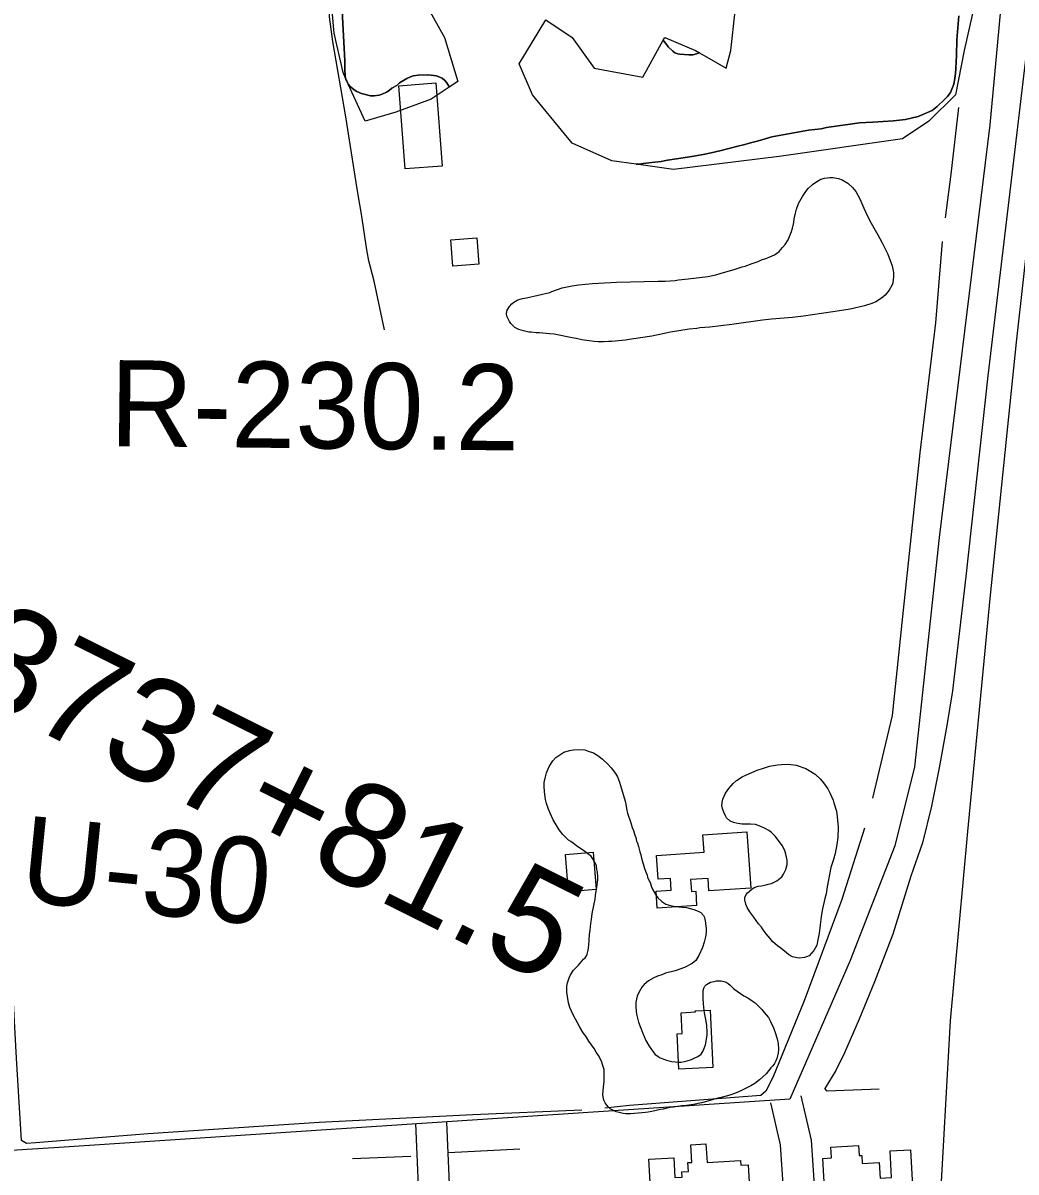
# Model space of a CAD drawing. Extents: x 3313447 to 3351316, y 703786 to 729172.
# Drawn here: x 3320930 to 3321887, y 714073 to 715181 of the extents above; entities that cross this region are included whole.
import ezdxf

# ---------------------------------------------------------------- set-up
doc = ezdxf.new("R2010")
doc.units = 0
for name, color, linetype in [('V-BLDG-OTLN', 7, 'Continuous'), ('V-DTCH-CNTR', 7, 'Continuous'), ('V-LEVE-TOET', 7, 'Continuous'), ('V-RIVR-RANG-IDEN', 7, 'Continuous'), ('V-ROAD-CNTR', 7, 'Continuous'), ('V-SITE-VEGE', 7, 'Continuous'), ('V-SURV-IDEN', 7, 'Continuous'), ('V-TOPO-SHOR', 7, 'Continuous')]:
    doc.layers.add(name, color=color, linetype=linetype)

msp = doc.modelspace()

# ---------------------------------------------------------------- linework, layer by layer
at = {"layer": 'V-BLDG-OTLN'}
for points in [[(3321327.5, 715123.3), (3321333.6, 715043.1), (3321297.9, 715040.4), (3321291.7, 715120.5)], [(3321342, 714972.1), (3321367.1, 714974), (3321369, 714948.5), (3321343.9, 714946.7)], [(3321627.2, 714401.1), (3321630.9, 714346.8), (3321590.7, 714344.1), (3321589.9, 714356.2), (3321573, 714355), (3321573.8, 714343.5), (3321577.9, 714343.7), (3321578.8, 714330), (3321540.8, 714327.4), (3321539.7, 714343.9), (3321554.3, 714344.8), (3321553.5, 714356.1), (3321541.7, 714355.3), (3321540.1, 714378.2), (3321585.9, 714381.3), (3321584.7, 714398.2)], [(3321455.2, 714343.2), (3321452.3, 714379.1), (3321479.1, 714381.3), (3321482, 714345.3)], [(3321594.4, 714173.8), (3321561.7, 714172.3), (3321560.1, 714206.2), (3321564.7, 714206.5), (3321563.8, 714226.6), (3321577.6, 714227.3), (3321577.5, 714228.5), (3321591.8, 714229.2)], [(3321622.6, 714051.2), (3321572.9, 714048.4), (3321572.5, 714055.3), (3321565.3, 714054.9), (3321564.9, 714061.4), (3321558.3, 714061), (3321559.1, 714047.8), (3321534.9, 714046.4), (3321532.7, 714085.2), (3321556.7, 714086.5), (3321557.7, 714067.7), (3321564.8, 714068.1), (3321564.5, 714073), (3321570.9, 714073.4), (3321570.4, 714082), (3321574.1, 714082.2), (3321573.1, 714099.3), (3321587.8, 714100.1), (3321588.8, 714082), (3321621.1, 714083.9), (3321621.4, 714079.5), (3321628.4, 714079.9), (3321629.6, 714057.3), (3321622.3, 714056.9)], [(3321703.7, 714029.1), (3321700.5, 714086.1), (3321708.9, 714086.6), (3321708.3, 714096.9), (3321734.7, 714098.4), (3321735.3, 714088.9), (3321737.9, 714089), (3321738.3, 714081.2), (3321754.7, 714082.1), (3321755.6, 714066.9), (3321766.7, 714067.5), (3321765.3, 714093.3), (3321784.8, 714094.4), (3321789.4, 714012.3), (3321711.6, 714007.9), (3321710.4, 714029.5)]]:
    msp.add_lwpolyline(points, close=True, dxfattribs=at)
at = {"layer": 'V-DTCH-CNTR'}
msp.add_lwpolyline([(3321278.1, 714885.1), (3321267.9, 714932), (3321262.8, 714951.9), (3321260.9, 714962.5), (3321255.9, 714996.8), (3321252.7, 715015.3), (3321250.8, 715027.2), (3321240.7, 715090.7), (3321228.1, 715163.4), (3321225, 715187.2), (3321223.1, 715285.6), (3321220.9, 715424.3), (3321216.9, 715500.2), (3321214.4, 715520.1), (3321213.2, 715540.5), (3321213.3, 715547.8), (3321226.3, 715603.8), (3321257.4, 715706.6), (3321261.6, 715725), (3321262.3, 715737.6), (3321261.8, 715750.2)], dxfattribs=at)
at = {"layer": 'V-LEVE-TOET'}
msp.add_lwpolyline([(3322242.7, 717499.5), (3322230.5, 717440.1), (3322212.4, 717370.3), (3322147.4, 717157.3), (3322074.9, 716954), (3322061.5, 716913.3), (3322054.1, 716881.2), (3322048.8, 716841), (3322042.9, 716778.8), (3322030.3, 716614.9), (3322015.8, 716405.6), (3321998.4, 716162.8), (3321980.6, 715959.1), (3321966.7, 715741.7), (3321955.2, 715572.1), (3321934, 715358.8), (3321913.8, 715115), (3321886.9, 714873.2), (3321861.3, 714626.1), (3321839.8, 714401.3), (3321823, 714218.9), (3321812.7, 714029.1)], dxfattribs=at)
at = {"layer": 'V-ROAD-CNTR'}
for points in [[(3322085.6, 717177.5), (3322015.6, 716972.5), (3322011.3, 716929.5), (3321982.2, 716607.2), (3321954.7, 716329.7), (3321908.3, 715769.3), (3321893.7, 715433.5), (3321861.3, 715083), (3321812.5, 714684.9), (3321788.9, 714463.9), (3321769.7, 714387.5), (3321726.9, 714277.1), (3321668.7, 714143.2), (3320964.4, 714096.5), (3320401.5, 714061.2), (3320028.1, 714032.5), (3319482.1, 714000.4), (3319185.8, 713985.2), (3318680.1, 713949.5), (3318059.6, 713912.2), (3317624.2, 713887.5), (3317588.3, 713886.1)], [(3321378, 713400.2), (3321715.2, 713421.7), (3321740.9, 713461), (3321742.6, 713511.5), (3321708.4, 713764.9), (3321705.6, 713861.5), (3321689.5, 714103.7), (3321679.7, 714146.3)], [(3321677.1, 713810.2), (3321675.6, 713860.1), (3321659.7, 714099.3), (3321650.4, 714139.6)], [(3321337.8, 714120.9), (3321351.7, 713800.1), (3321353.4, 713784.7)], [(3321307.9, 714119.6), (3321321.8, 713797.8), (3321331.8, 713706.9), (3321334, 713663.7)]]:
    msp.add_lwpolyline(points, dxfattribs=at)
at = {"layer": 'V-SITE-VEGE'}
for points in [[(3321230.5, 715319.4), (3321239.8, 715144.7), (3321239.7, 715136.6), (3321240.1, 715130.2), (3321240.4, 715128.1), (3321238.1, 715133.3), (3321229.6, 715171.5), (3321225.3, 715218.2)], [(3321336.2, 715125.6), (3321333.6, 715128.1), (3321328.2, 715130.1), (3321323.1, 715130.9), (3321319.7, 715131.2), (3321310.5, 715130.8), (3321305.6, 715130.1), (3321303, 715129.3), (3321299.4, 715127.7), (3321292.5, 715123.3), (3321289.7, 715121), (3321285.2, 715118.2), (3321282.6, 715116.2), (3321279.8, 715114.6), (3321275.7, 715112.6), (3321272.7, 715111.6), (3321268.1, 715110.9), (3321264.6, 715110.9), (3321255.8, 715113), (3321251.2, 715115.2), (3321248.8, 715116.8), (3321245, 715119.9), (3321243.1, 715122.2), (3321240.4, 715128.1), (3321240.1, 715130.2), (3321239.7, 715136.6), (3321239.8, 715144.7), (3321230.5, 715319.4)], [(3321862.2, 715269.2), (3321836.7, 715154.5), (3321828.2, 715112), (3321802.7, 715086.5), (3321777.3, 715069.5), (3321658.4, 715052.5), (3321556.5, 715039.8), (3321520.6, 715044.9), (3321523, 715045.1), (3321527.3, 715045.5), (3321538.5, 715046.8), (3321544.6, 715047.7), (3321547.4, 715048.3), (3321550.6, 715048.7), (3321559.5, 715050), (3321574.2, 715052.5), (3321585.1, 715054.3), (3321592.7, 715055.8), (3321602.6, 715058.3), (3321617.1, 715061.9), (3321625.2, 715064), (3321630.6, 715065.6), (3321638.5, 715067.5), (3321651.2, 715071.4), (3321686.6, 715077.8), (3321698.9, 715079.1), (3321704, 715080.3), (3321735.8, 715084.9), (3321748.5, 715085.4), (3321768.6, 715086.8), (3321780.1, 715088.1), (3321792.4, 715090.9), (3321805.7, 715096.8), (3321810.5, 715100.6), (3321818, 715107.8), (3321820.7, 715110.2), (3321823.5, 715114.2), (3321826.6, 715122), (3321827.4, 715125.8), (3321828.3, 715132.4), (3321828.5, 715137.2), (3321829.4, 715150.1), (3321829.5, 715165), (3321831.5, 715188.1)], [(3321314.5, 715205.5), (3321335.7, 715167.2), (3321348.5, 715124.8), (3321340.3, 715119.3), (3321340, 715120.2), (3321338, 715123.6), (3321336.2, 715125.6)], [(3321559.5, 715050), (3321550.6, 715048.7), (3321547.4, 715048.3), (3321544.6, 715047.7), (3321538.5, 715046.8), (3321527.3, 715045.5), (3321523, 715045.1), (3321520.6, 715044.9), (3321497.1, 715048.3), (3321458.8, 715065.3), (3321420.6, 715112), (3321407.9, 715141.8), (3321433.4, 715184.2), (3321458.8, 715167.2), (3321480.1, 715137.5), (3321526.8, 715129), (3321546.5, 715164.5), (3321547.5, 715163.2), (3321549.1, 715161.4), (3321551.5, 715158.3), (3321555.9, 715153.9), (3321557.9, 715152.4), (3321560.7, 715151.4), (3321562.7, 715151), (3321571.3, 715150.3), (3321575, 715150.5), (3321578.8, 715151.3), (3321581.5, 715152.4), (3321607.4, 715137.5), (3321611.7, 715154.5), (3321615.9, 715192.7)], [(3321831.5, 715188.1), (3321829.5, 715165), (3321829.4, 715150.1), (3321828.5, 715137.2), (3321828.3, 715132.4), (3321827.4, 715125.8), (3321826.6, 715122), (3321823.5, 715114.2), (3321820.7, 715110.2), (3321818, 715107.8), (3321810.5, 715100.6), (3321805.7, 715096.8), (3321792.4, 715090.9), (3321780.1, 715088.1), (3321768.6, 715086.8), (3321748.5, 715085.4), (3321735.8, 715084.9), (3321704, 715080.3), (3321698.9, 715079.1), (3321686.6, 715077.8), (3321651.2, 715071.4), (3321638.5, 715067.5), (3321630.6, 715065.6), (3321625.2, 715064), (3321617.1, 715061.9), (3321602.6, 715058.3), (3321592.7, 715055.8), (3321585.1, 715054.3), (3321574.2, 715052.5), (3321559.5, 715050)], [(3321412, 714884.1), (3321407.5, 714885.4), (3321403.6, 714887.5), (3321399.7, 714891.4), (3321398.4, 714893.4), (3321396.8, 714896.5), (3321396, 714898.5), (3321395.5, 714901), (3321396.1, 714904.2), (3321398.4, 714907.8), (3321400.6, 714910.3), (3321402.6, 714911.8), (3321406.5, 714914), (3321411, 714915.3), (3321414.9, 714916), (3321437.3, 714921.2), (3321439.1, 714922.1), (3321449.2, 714925.8), (3321458.9, 714927.8), (3321464.9, 714928.5), (3321478.4, 714929.8), (3321501.7, 714931.2), (3321541.7, 714932), (3321548.4, 714932.2), (3321558.2, 714932.9), (3321561.3, 714933.3), (3321570.5, 714934.3), (3321589.5, 714936.7), (3321597.2, 714938.4), (3321601.6, 714939.7), (3321615.8, 714943.7), (3321622.6, 714945.9), (3321625.6, 714946.7), (3321632.4, 714949.2), (3321638.2, 714951.1), (3321641.4, 714952.6), (3321646.3, 714954.5), (3321649.5, 714955.6), (3321653.7, 714957.5), (3321658.4, 714960.9), (3321661.7, 714964.6), (3321664, 714967.4), (3321666.9, 714971.9), (3321668.4, 714975.2), (3321670.2, 714980), (3321671.3, 714983.4), (3321672.4, 714988.8), (3321672.9, 714992.4), (3321674, 714997.9), (3321675, 715001.7), (3321676.9, 715007.2), (3321680.7, 715013.9), (3321684, 715018.5), (3321686.4, 715021.5), (3321690.5, 715025.4), (3321693.8, 715027.7), (3321698.6, 715030.4), (3321702.1, 715031.4), (3321707.2, 715032.3), (3321710.5, 715032.3), (3321715.6, 715031.2), (3321719.2, 715029.8), (3321724.5, 715026.8), (3321729.1, 715022.4), (3321732.3, 715018.5), (3321736, 715011.7), (3321739.9, 715002.5), (3321742, 714998.4), (3321744.8, 714992.3), (3321746.9, 714988.2), (3321753.4, 714976.9), (3321757.4, 714969.7), (3321760.9, 714962.8), (3321763, 714958.3), (3321767.1, 714946.8), (3321768.4, 714940.4), (3321768.6, 714936.2), (3321767.9, 714930.6), (3321767.1, 714928.7), (3321764.5, 714923.6), (3321760.4, 714918.6), (3321756.9, 714915.7), (3321751.4, 714912.3), (3321747.5, 714910.6), (3321740.5, 714908.4), (3321726.7, 714905.3), (3321712.2, 714902.8), (3321699, 714901.1), (3321681.7, 714898.5), (3321671.1, 714897.2), (3321651, 714895.6), (3321642.4, 714894.6), (3321612.7, 714890.5), (3321591.4, 714887.8), (3321582, 714887), (3321579, 714886.6), (3321571.5, 714885.9), (3321553.6, 714883), (3321546.2, 714881.4), (3321535.6, 714879), (3321515.9, 714876.1)], [(3321515.9, 714876.1), (3321510.2, 714875.4), (3321506.9, 714874.8), (3321496.7, 714874), (3321493.9, 714873.9), (3321489.1, 714873.8), (3321483.8, 714873.8), (3321480.2, 714874.1), (3321475.3, 714874.6), (3321468, 714875.7), (3321462.6, 714876.7), (3321458.8, 714877.6), (3321441.6, 714880.9), (3321437, 714881.5), (3321427.5, 714882.2), (3321424.2, 714882.2), (3321419.3, 714882.9), (3321417.2, 714883), (3321412, 714884.1)], [(3321476.7, 714377.9), (3321474.4, 714379.6), (3321471.2, 714382.2), (3321463.1, 714387.6), (3321459.8, 714390), (3321457.7, 714391.6), (3321455.4, 714393), (3321452.4, 714395.9), (3321449.8, 714398.5), (3321446.4, 714402.9), (3321440.6, 714412.5), (3321437.6, 714418.9), (3321436, 714422.8), (3321434, 714428.4), (3321433.1, 714432.2), (3321432.2, 714439.7), (3321431.8, 714445), (3321432, 714448.5), (3321433, 714454.1), (3321434, 714458.1), (3321436.6, 714464.1), (3321440.1, 714469.5), (3321443, 714472.7), (3321447.9, 714475.9), (3321450.9, 714477.8), (3321456.3, 714479.4), (3321460, 714480), (3321464.7, 714480.5), (3321471.2, 714480), (3321474.3, 714479), (3321479.4, 714477.1), (3321484.5, 714474), (3321488.2, 714471), (3321493.3, 714466.2), (3321496.5, 714462.7), (3321500.5, 714457.3), (3321502.5, 714454), (3321504.4, 714449.1), (3321505.5, 714445.6), (3321509.8, 714430.7), (3321510.5, 714427.6), (3321511.4, 714421.5), (3321512.1, 714419), (3321515.3, 714409.6), (3321516.6, 714405.2), (3321517.8, 714402.4), (3321519.1, 714397.9), (3321520.3, 714395.6)], [(3321696.9, 714303.2), (3321695.7, 714296.9), (3321694.5, 714291.8), (3321693, 714288.8), (3321691.6, 714286.7), (3321689.5, 714283.9), (3321687.2, 714281.6), (3321684.8, 714280.4), (3321682.7, 714279.7), (3321677.8, 714279.3), (3321675.5, 714279.6), (3321671.3, 714280.5), (3321669.4, 714281.5), (3321667.3, 714282.7), (3321659.9, 714288.8), (3321656.7, 714291.1), (3321652.3, 714295.1), (3321649.7, 714298.2), (3321645.8, 714302.7), (3321642.8, 714306.4), (3321641.2, 714309), (3321638.4, 714312.3), (3321634, 714318.6), (3321631.9, 714321.2), (3321630.1, 714323.8), (3321627.6, 714328.2), (3321626.2, 714331.3), (3321625.3, 714335.5), (3321625.3, 714337.8), (3321626.5, 714340.6), (3321627.7, 714342.2), (3321631.9, 714345.9), (3321634.2, 714347.3), (3321638.2, 714348.5), (3321641.2, 714348.9), (3321645.7, 714349.8), (3321647.8, 714350.5), (3321651.1, 714351.1), (3321656.2, 714353.9), (3321660.9, 714357.8), (3321662.6, 714360.2), (3321664.7, 714364.6), (3321665.9, 714369.7), (3321665.9, 714373.7), (3321664.8, 714379.5), (3321663.7, 714383), (3321661.2, 714387.9), (3321656.8, 714394), (3321654.5, 714396.9), (3321651, 714400.4), (3321648.4, 714402.3), (3321644.7, 714404.4), (3321640.8, 714406.1), (3321635.6, 714408), (3321630.7, 714408.5), (3321628.4, 714408.3), (3321622.8, 714408.3), (3321620.5, 714408.8), (3321616.8, 714409.3), (3321614.2, 714410), (3321610.9, 714411.7), (3321607.7, 714414.5), (3321606.5, 714416.4), (3321604.9, 714420.1), (3321604, 714422.7), (3321603.1, 714425.7), (3321603.4, 714429.2), (3321604.1, 714432.7), (3321606.5, 714438.3), (3321609.8, 714442.7), (3321614, 714447.8), (3321617.3, 714450.6), (3321622.7, 714454), (3321626.7, 714456.1), (3321637.2, 714460.5), (3321643.1, 714462.5), (3321648.9, 714464.3), (3321656.6, 714465.7), (3321660.6, 714466.1), (3321666, 714466.3), (3321669.5, 714466), (3321674.6, 714465.3), (3321683.9, 714462), (3321687.4, 714460.3), (3321693, 714456.8), (3321698.1, 714451.8), (3321701.1, 714448.3), (3321705.2, 714442.4), (3321707.3, 714438.7), (3321710.3, 714431.6), (3321710.9, 714429.1), (3321713.7, 714421.1), (3321714.3, 714415.5), (3321715.2, 714405.7), (3321714.9, 714395.7), (3321713.9, 714388.9), (3321712.2, 714380.1), (3321710.7, 714374.5), (3321708.1, 714366.8), (3321704.5, 714347.9), (3321703.5, 714341.2)], [(3321520.3, 714395.6), (3321521, 714392.1), (3321521.9, 714390), (3321522.8, 714386.9), (3321524.1, 714381.8), (3321525.1, 714379), (3321525.7, 714375.7), (3321528.7, 714365.6), (3321530.1, 714361.4), (3321531, 714359.3), (3321531.6, 714357.2), (3321532.8, 714354.4), (3321533.9, 714352.1), (3321535.3, 714348.1), (3321536.2, 714345.8), (3321539.7, 714339.7), (3321541.5, 714337.5), (3321545.2, 714334), (3321549.2, 714331.4), (3321551.3, 714330.7), (3321556.4, 714329.5), (3321564.8, 714328.3), (3321569, 714328), (3321576, 714326.3), (3321580.4, 714324.4), (3321582.7, 714323.2), (3321585.3, 714320.4), (3321586.4, 714318.3), (3321587.1, 714315.3), (3321587.7, 714310.3), (3321588, 714308), (3321587.9, 714304.7), (3321587.7, 714301), (3321586.2, 714294.7), (3321584.3, 714289.4), (3321580.8, 714281.9), (3321577.9, 714277.1), (3321574.6, 714274.1), (3321567.1, 714270.1), (3321558, 714266.9), (3321548.9, 714264.7), (3321545.1, 714263.1), (3321541.2, 714261.9), (3321537.4, 714260.3), (3321532.5, 714257.3), (3321528.3, 714253.9), (3321525.9, 714251.1), (3321523.1, 714246.2), (3321521.4, 714242.5), (3321520.2, 714236.7), (3321520.2, 714232.9), (3321520.6, 714227.6), (3321521.3, 714223.8), (3321522.9, 714217.5), (3321524.5, 714213.3), (3321526.5, 714207.5), (3321528.1, 714203.5), (3321529.9, 714199.7), (3321532.9, 714194.3), (3321537.6, 714188), (3321538.9, 714186.4), (3321541.3, 714184.7), (3321543.1, 714183.5), (3321546.1, 714182.1), (3321549.6, 714180.9), (3321555, 714179.5), (3321561.3, 714179), (3321563.6, 714178.9), (3321567.1, 714179.4), (3321569.7, 714180.1), (3321573.7, 714181.4), (3321576.5, 714182.6), (3321580, 714184.4), (3321583.3, 714186.5), (3321585.2, 714189.7), (3321586.4, 714193.2), (3321587.3, 714195.6), (3321589, 714204.9), (3321589, 714207.7), (3321588.6, 714214.2), (3321588, 714218.6), (3321587.3, 714221.5), (3321586.4, 714226.6), (3321585.7, 714231.7), (3321585.5, 714235.5), (3321585.1, 714240.4), (3321585.2, 714248.1), (3321585.6, 714250.2), (3321586.6, 714252.3), (3321588.2, 714253.9), (3321592.2, 714255.9), (3321595.7, 714256.6), (3321598.1, 714257.3), (3321600.4, 714257.5), (3321602.5, 714257.5), (3321605.1, 714256.8), (3321607.4, 714256.1), (3321609.2, 714254.9), (3321611.1, 714253.2), (3321614.8, 714249.5), (3321624.3, 714242.9)], [(3321624.3, 714242.9), (3321628.3, 714241), (3321632.4, 714238.1), (3321635.2, 714236), (3321641.5, 714229.7), (3321644, 714226.8), (3321648, 714221.9), (3321650, 714218.2), (3321652.8, 714212.1), (3321654.6, 714207.6), (3321656.4, 714201.3), (3321657.3, 714196.9), (3321657.7, 714191), (3321657.5, 714187.8), (3321656.3, 714183.3), (3321655.3, 714180.8), (3321653.7, 714177.5), (3321652.3, 714175.4), (3321650.4, 714173.4), (3321645.7, 714167.6), (3321639.5, 714162), (3321634.9, 714158.3), (3321631.1, 714156), (3321621.5, 714151.2), (3321616.3, 714148.9), (3321610.7, 714147.1), (3321602.5, 714144.8), (3321599.3, 714144.1), (3321594.8, 714143), (3321589.7, 714141.4), (3321583.4, 714139.8), (3321575.7, 714138.2), (3321568.9, 714137.1), (3321564.5, 714136.7), (3321556.5, 714135.6), (3321552.5, 714135.2), (3321546.5, 714133.6), (3321544.1, 714133.4), (3321535.5, 714131.3), (3321532.2, 714130.7), (3321529.4, 714130.2), (3321522.4, 714129.6), (3321515.4, 714129.2), (3321510.7, 714129.2), (3321507.9, 714129.4), (3321504, 714130.4), (3321501.2, 714130.9), (3321495.6, 714134), (3321493.3, 714136.1), (3321490.5, 714139.8), (3321489.4, 714142.2), (3321488.7, 714145.5), (3321488.5, 714147.6), (3321488.7, 714151.3), (3321489.2, 714154.8), (3321489.7, 714160.2), (3321489.8, 714168.8), (3321489.6, 714171.8), (3321488.2, 714176.7), (3321487.1, 714180), (3321484.3, 714185.2), (3321482, 714188.7), (3321480.2, 714192), (3321474.9, 714199.2), (3321471.9, 714203.9), (3321469.6, 714207.2), (3321466.1, 714212.8), (3321459.9, 714224.6), (3321456.7, 714231.6), (3321455.3, 714236), (3321454.2, 714242.3), (3321453.8, 714246.5), (3321453.8, 714252.1), (3321454.3, 714255.4), (3321455.8, 714260.3), (3321457.2, 714263.1), (3321460.2, 714267.5), (3321462.4, 714270), (3321465, 714272.6), (3321469.7, 714278.1), (3321471.3, 714279.5), (3321472.5, 714281.4), (3321473.4, 714283.2), (3321474.4, 714287), (3321474.9, 714291.6), (3321475.7, 714301.9), (3321476.2, 714306.3), (3321476.7, 714312.6), (3321477.4, 714316.6), (3321478.2, 714322.4), (3321480.9, 714336.2), (3321481.3, 714339.9), (3321482.3, 714345.5), (3321483.6, 714354.6), (3321483.6, 714357.8), (3321483.4, 714362.3), (3321482.7, 714364.8), (3321482.3, 714368.3), (3321480, 714373), (3321478.8, 714375.1), (3321476.7, 714377.9)], [(3321703.5, 714341.2), (3321702.3, 714336.7), (3321700.1, 714326.7), (3321699.6, 714323.2), (3321698.9, 714319), (3321697.9, 714311.4), (3321697.4, 714308.6), (3321696.9, 714303.2)]]:
    msp.add_lwpolyline(points, dxfattribs=at)
for points in [[(3321581.5, 715152.4), (3321578.8, 715151.3), (3321575, 715150.5), (3321571.3, 715150.3), (3321562.7, 715151), (3321560.7, 715151.4), (3321557.9, 715152.4), (3321555.9, 715153.9), (3321551.5, 715158.3), (3321549.1, 715161.4), (3321547.5, 715163.2), (3321546.5, 715164.5), (3321548, 715167.2), (3321577.7, 715154.5)], [(3321243.1, 715122.2), (3321243, 715122.3), (3321240.6, 715126.8), (3321240.4, 715128.1)], [(3321340.3, 715119.3), (3321323, 715107.8), (3321289, 715095), (3321259.3, 715086.5), (3321243.1, 715122.2), (3321245, 715119.9), (3321248.8, 715116.8), (3321251.2, 715115.2), (3321255.8, 715113), (3321264.6, 715110.9), (3321268.1, 715110.9), (3321272.7, 715111.6), (3321275.7, 715112.6), (3321279.8, 715114.6), (3321282.6, 715116.2), (3321285.2, 715118.2), (3321289.7, 715121), (3321292.5, 715123.3), (3321299.4, 715127.7), (3321303, 715129.3), (3321305.6, 715130.1), (3321310.5, 715130.8), (3321319.7, 715131.2), (3321323.1, 715130.9), (3321328.2, 715130.1), (3321333.6, 715128.1), (3321336.2, 715125.6), (3321338, 715123.6), (3321340, 715120.2)]]:
    msp.add_lwpolyline(points, close=True, dxfattribs=at)
at = {"layer": 'V-TOPO-SHOR'}
for p, q in [((3321303.3, 714087.8), (3321247.1, 714085.7)), ((3321339.5, 714091.9), (3321408.5, 714095.4))]:
    msp.add_line(p, q, dxfattribs=at)
for points in [[(3321965.8, 716064.3), (3321952.9, 715886.9), (3321939, 715689.6), (3321927.1, 715523.3), (3321913.6, 715329.8), (3321899.9, 715181.3), (3321879.1, 715005), (3321859.5, 714840.8), (3321838.1, 714647.3), (3321825.4, 714537), (3321819.8, 714503.6), (3321812.7, 714462.8), (3321805.2, 714425.8), (3321796.5, 714390.3), (3321785.3, 714358.4), (3321768, 714302.3), (3321750.3, 714256.4), (3321735.5, 714220.4), (3321721.2, 714187.8), (3321712.8, 714170.7), (3321702.5, 714153.6)], [(3320941.5, 714101.2), (3320932.8, 714100.6), (3320928.1, 714103.3), (3320923.3, 714182.7), (3320913.9, 714354.8), (3320903.7, 714502.7), (3320892.6, 714723.2), (3320881.9, 714902.8), (3320869.5, 715115.9), (3320865.8, 715160.3), (3320863.8, 715163.6), (3320854.8, 715164.4)], [(3321831.1, 715099.8), (3321823.7, 715035.2), (3321818.2, 714993.3)], [(3321815.4, 714970.5), (3321809.1, 714892.1), (3321794, 714766.6), (3321777.3, 714608.8), (3321767.2, 714513.4), (3321748.2, 714433.4)], [(3321740.6, 714404.6), (3321718.8, 714335.7), (3321682.4, 714237.9), (3321652.2, 714164.2), (3321645.4, 714150.8), (3321640.7, 714146.8), (3321514.2, 714137.1), (3321490.4, 714134.4)], [(3321754.7, 714152.8), (3321704.5, 714150.9), (3321702.5, 714153.6)], [(3321468.2, 714132.5), (3321363, 714128.2), (3321215.1, 714120.6), (3321050.3, 714109.8), (3320941.5, 714101.2)]]:
    msp.add_lwpolyline(points, dxfattribs=at)

# ---------------------------------------------------------------- texts
at = {"layer": 'V-RIVR-RANG-IDEN'}
for s, rotation, p in [('R-230.2', 359.3771, (3321012.9, 714773.1)), ('U-30', 354.328, (3320924.7, 714334.3))]:
    msp.add_text(s, height=83, rotation=rotation, dxfattribs=at).set_placement(p)
at = {"layer": 'V-SURV-IDEN'}
msp.add_text('3737+81.5', height=100, rotation=333.4136, dxfattribs=at).set_placement((3320866.3, 714537.8))

doc.saveas('drawing.dxf')
